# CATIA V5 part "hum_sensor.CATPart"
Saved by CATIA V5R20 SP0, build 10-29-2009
Part number: hum_sensor
Bounding box of the stored display mesh (mm): x -13.08 to 14, y -20 to 4.75, z 0 to 12.4
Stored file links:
  C:\Users\user\OneDrive\바탕 화면\지혜 카티아\hum_sensor.CATPart
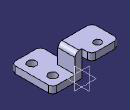
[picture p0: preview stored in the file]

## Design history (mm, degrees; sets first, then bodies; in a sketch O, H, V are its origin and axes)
Body1 (main body)
  Sketch1 on xy-plane, origin (0, 0, 0), H (1, 0, 0), V (0, 1, 0)
    line L1 (0, 0) -> (14, 0)
    line L2 (14, 0) -> (14, -20)
    line L3 (14, -20) -> (0, -20)
    line L4 (0, -20) -> (0, 0)
    length L2 = 20
    length L1 = 14
    horizontal: L1 H, L3 H
    vertical: L2 V, L4 V
  Pad1: profile Sketch1, direction (0, 0, 1), length 3.3
  Sketch2 on end face of Pad1, origin (0, 0, 3.3), H (1, 0, 0), V (0, 1, 0)
    line L1 (0, 0) -> (3.3, 0)
    line L2 (3.3, 0) -> (3.3, -8.25)
    line L3 (3.3, -8.25) -> (0, -8.25)
    line L4 (0, -8.25) -> (0, 0)
    reference projected line E1 (14, 0) -> (0, 0) from edge [face of Pad1 from Sketch1.L1 | end face of Pad1]
    reference projected line E2 (0, 0) -> (0, -20) from edge [face of Pad1 from Sketch1.L4 | end face of Pad1]
    length L2 = 8.25
    length L3 = 3.3
    horizontal: L1 H, L3 H
    vertical: L2 V, L4 V
    coincidence: L1 E1, L4 E2
  Pad2: profile Sketch2, direction (0, 0, 1), length 9.1
  Sketch3 on face of Pad2, origin (0, 0, 0), H (0, -1, 0), V (0, 0, 1)
    line L1 (8.25, 9.1) -> (-4.75, 9.1)
    line L2 (-4.75, 9.1) -> (-4.75, 12.4)
    line L3 (-4.75, 12.4) -> (8.25, 12.4)
    line L4 (8.25, 12.4) -> (8.25, 9.1)
    reference projected line E1 (0, 12.4) -> (8.25, 12.4) from edge [face of Pad2 | end face of Pad2]
    reference projected line E2 (8.25, 3.3) -> (8.25, 12.4) from edge [face of Pad2 from Sketch2.L3 | face of Pad2]
    length L1 = 13
    length L2 = 3.3
    horizontal: L1 H, L3 H
    vertical: L2 V, L4 V
    coincidence: L3 E1, E2 L4
  Pad3: profile Sketch3, direction (-1, 0, 0), length 13.08
  Sketch4 on face of Pad3, origin (-6.0761, -2.2196, 12.4), H (1, 0, 0), V (0, 1, 0)
    point P1 (-0.4639, 3.3296)
    reference projected line E1 (6.0761, 6.9696) -> (-7.0039, 6.9696) from edge [face of Pad3 from Sketch3.L2 | face of Pad3 from Sketch3.L3]
    reference projected line E2 (6.0761, 2.2196) -> (6.0761, 6.9696) from edge [start face of Pad3 | face of Pad3]
    distance P1 E1 = 3.64
    distance P1 E2 = 6.54
  Hole1: placed by Sketch4, at (-6.54, 1.11, 12.4) direction (0, 0, -1), diameter 3.48, depth 10
  Sketch5 on end face of Pad1, origin (12.0942, -9.5423, 3.3), H (1, 0, 0), V (0, 1, 0)
    point P1 (-3.0942, 4.5423)
    reference projected line E1 (1.9058, -10.4577) -> (1.9058, 9.5423) from edge [face of Pad1 from Sketch1.L2 | end face of Pad1]
    reference projected line E2 (1.9058, 9.5423) -> (-12.0942, 9.5423) from edge [face of Pad2 | end face of Pad1]
    distance P1 E1 = 5
    distance P1 E2 = 5
  Hole2: placed by Sketch5, at (9, -5, 3.3) direction (0, 0, -1), diameter 4.2, depth 10
  Sketch6 on end face of Pad1, origin (8.9697, -13.0127, 3.3), H (1, 0, 0), V (0, 1, 0)
    point P1 (0.0303, -1.9873)
    reference projected line E1 (-8.9697, -6.9873) -> (5.0303, -6.9873) from edge [face of Pad1 from Sketch1.L3 | end face of Pad1]
    reference projected line E2 (5.0303, -6.9873) -> (5.0303, 13.0127) from edge [face of Pad1 from Sketch1.L2 | end face of Pad1]
    distance P1 E1 = 5
    distance P1 E2 = 5
  Hole3: placed by Sketch6, at (9, -15, 3.3) direction (0, 0, -1), diameter 4.2, depth 10
  Fillet1: radius 2, on edge [face of Pad2 | face of Pad1 from Sketch1.L2]; edge [face of Pad2 from Sketch2.L2 | face of Pad3]; edge [start face of Pad3 | face of Pad3 from Sketch3.L2]; edge [face of Pad3 from Sketch3.L2 | end face of Pad3]; edge [face of Pad3 | end face of Pad3]
  Fillet2: radius 2, on edge [face of Pad1 from Sketch1.L3 | face of Pad2]; edge [face of Pad1 from Sketch1.L2 | face of Pad1 from Sketch1.L3]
